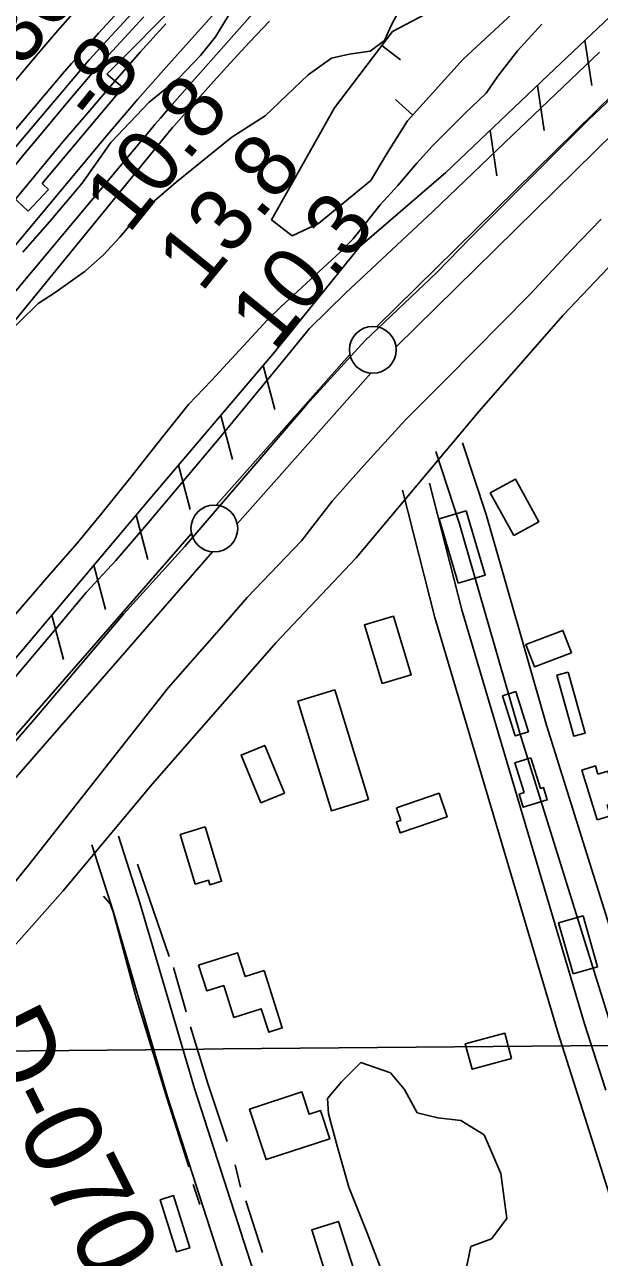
# Model space of a CAD drawing. Extents: x 3598634 to 3636690, y 517270 to 542944.
# Drawn here: x 3608565 to 3609179, y 528569 to 529886 of the extents above; entities that cross this region are included whole.
import ezdxf

# ---------------------------------------------------------------- set-up
doc = ezdxf.new("R2010")
doc.units = 0
for name, color, linetype in [('V-BLDG-OTLN', 7, 'Continuous'), ('V-BORW-LINE', 7, 'Continuous'), ('V-FLOD-BASE', 7, 'Continuous'), ('V-GRID-MAJR', 7, 'Continuous'), ('V-LEVE-TOET', 7, 'Continuous'), ('V-RIVR-EDGE', 7, 'Continuous'), ('V-RIVR-RANG', 7, 'Continuous'), ('V-RIVR-RANG-IDEN', 7, 'Continuous'), ('V-ROAD-CNTR', 7, 'Continuous'), ('V-RRAP-FSHR', 7, 'Continuous'), ('V-RRAP-RVMT', 7, 'Continuous'), ('V-SITE-VEGE', 7, 'Continuous'), ('V-SURV-LINE', 7, 'Continuous'), ('V-TOPO-DPTH', 7, 'Continuous'), ('V-TOPO-MINR', 7, 'Continuous'), ('V-TOPO-SHOR', 7, 'Continuous'), ('V-TOPO-WATR', 7, 'Continuous')]:
    doc.layers.add(name, color=color, linetype=linetype)

msp = doc.modelspace()

# ---------------------------------------------------------------- linework, layer by layer
at = {"layer": 'V-BLDG-OTLN'}
for points in [[(3609087.4, 529339.9), (3609062.3, 529385.6), (3609089.2, 529400.4), (3609114.2, 529354.7)], [(3609028, 529289.1), (3609007.8, 529357.9), (3609036.5, 529366.3), (3609056.7, 529297.5)], [(3608946.7, 529181.8), (3608927.8, 529244.4), (3608958.8, 529253.8), (3608977.6, 529191.1)], [(3609148.9, 529214.5), (3609109.4, 529199.7), (3609100.4, 529223.6), (3609139.9, 529238.5)], [(3609145.5, 529194.1), (3609163.7, 529128.7), (3609151.6, 529125.4), (3609133.4, 529190.8)], [(3608896.3, 529175.1), (3608932, 529057.9), (3608892.5, 529045.9), (3608856.8, 529163)], [(3609089.6, 529173.2), (3609103.1, 529130.3), (3609088.9, 529125.8), (3609075.4, 529168.7)], [(3608817, 529054.2), (3608796.1, 529105.3), (3608821.4, 529115.7), (3608842.4, 529064.6)], [(3609105.7, 529102.4), (3609115.9, 529069.7), (3609119.1, 529070.7), (3609123.2, 529057.6), (3609097.5, 529049.6), (3609093.2, 529063.7), (3609098.4, 529065.4), (3609088.6, 529097.1)], [(3609176.3, 529036.1), (3609160.1, 529089.3), (3609174.6, 529093.7), (3609177.3, 529085), (3609187.9, 529088.2), (3609198, 529055.1), (3609187.2, 529051.8), (3609190.6, 529040.5)], [(3608962, 529049), (3609007.6, 529064.5), (3609016.2, 529039.3), (3608966.1, 529022.2), (3608962.1, 529033.9), (3608966.6, 529035.4)], [(3608757.7, 529028.5), (3608775.2, 528970.6), (3608762.6, 528966.7), (3608761.1, 528971.6), (3608747.1, 528967.4), (3608731, 529020.4)], [(3609150.7, 528871.5), (3609135.2, 528926), (3609161.4, 528933.4), (3609176.9, 528878.9)], [(3608820.6, 528875.1), (3608840.1, 528813.8), (3608825.6, 528809.2), (3608817.6, 528834.3), (3608788.3, 528825), (3608777.5, 528859), (3608759.4, 528853.3), (3608750.6, 528880.8), (3608792.1, 528894.1), (3608800.3, 528868.7)], [(3609085.1, 528781.1), (3609042.9, 528769.7), (3609035.6, 528796.6), (3609077.8, 528808.1)], [(3608890.9, 528695.3), (3608822.7, 528673), (3608805.1, 528727), (3608861, 528745.3), (3608868.7, 528721.5), (3608881, 528725.5)], [(3608723.7, 528634.6), (3608741.2, 528578.8), (3608727.2, 528574.4), (3608709.7, 528630.2)], [(3608892.4, 528531.9), (3608871.5, 528598), (3608900.1, 528607), (3608921, 528540.9)]]:
    msp.add_lwpolyline(points, close=True, dxfattribs=at)
at = {"layer": 'V-BORW-LINE'}
for p, q in [((3608946.5, 529863.6), (3608966.4, 529848.5)), ((3608979.4, 529789.4), (3608960.9, 529806.1))]:
    msp.add_line(p, q, dxfattribs=at)
for points in [[(3608934.7, 529719.3), (3608878.9, 529673.6), (3608850.6, 529660.4), (3608828.6, 529677.4), (3608895.8, 529796.9), (3608957.9, 529878.5), (3609006.5, 529904.3), (3609074.6, 529975.4), (3609115.4, 530005.8), (3609131.2, 529971.9), (3609090.7, 529902), (3609033.3, 529849.2), (3608973.8, 529783.2), (3608951, 529746.9), (3608934.7, 529719.3)], [(3608955, 529753.3), (3608973.8, 529783.2), (3609033.3, 529849.2), (3609090.7, 529902), (3609131.2, 529971.9), (3609115.4, 530005.8), (3609074.6, 529975.4), (3609006.5, 529904.3), (3608957.9, 529878.5), (3608899.4, 529801.6)], [(3608934.7, 529719.3), (3608951, 529746.9), (3608954.4, 529752.3)]]:
    msp.add_lwpolyline(points, dxfattribs=at)
at = {"layer": 'V-FLOD-BASE'}
msp.add_lwpolyline([(3608057.5, 528550.9), (3608164.4, 528673.2), (3608262.3, 528787.8), (3608368.5, 528912.2), (3608466.3, 529018.5), (3608577.4, 529146.3), (3608670.3, 529256.1), (3608736, 529328.3), (3608866, 529479.8), (3608928.2, 529547.9), (3609005.7, 529621.5), (3609041.3, 529658.3), (3609167, 529784), (3609227.1, 529840.9)], dxfattribs=at)
at = {"layer": 'V-GRID-MAJR'}
msp.add_spline([(3602797.9, 528737.7), (3608075.8, 528784.9), (3613353.8, 528832.9), (3618631.7, 528881.6), (3623909.7, 528931.1), (3629187.6, 528981.4), (3634465.5, 529032.5), (3634465.6, 529032.5)], degree=3, dxfattribs=at)
at = {"layer": 'V-LEVE-TOET'}
for points in [[(3609179.1, 529856.4), (3609077.8, 529759.9), (3609001, 529686.3), (3608908.1, 529599.5), (3608869, 529561.3), (3608835.5, 529520.3), (3608770.5, 529441.1), (3608695, 529351.4), (3608662.1, 529313.2), (3608630.7, 529279.2), (3608596.5, 529238.2), (3608544.7, 529177), (3608478.4, 529100.6), (3608366.6, 528972.8), (3608294.6, 528891.5), (3608219.1, 528804)], [(3608107.4, 528449.1), (3608214.3, 528584.6), (3608308.6, 528684.6), (3608364.5, 528749.9), (3608447.7, 528845.1), (3608484, 528888.9), (3608521.8, 528929.9), (3608569.3, 528988.2), (3608667.8, 529113.3), (3608718.2, 529177.2), (3608772.7, 529239.1), (3608802.7, 529273.8), (3608860.7, 529334.2), (3608893.5, 529376.6), (3608927.1, 529414.8), (3608971.8, 529463.5), (3609015.1, 529507.2), (3609104.5, 529597.5), (3609149.2, 529645.4), (3609180.6, 529678.1)]]:
    msp.add_lwpolyline(points, dxfattribs=at)
at = {"layer": 'V-RIVR-EDGE'}
msp.add_lwpolyline([(3608563, 529642.8), (3608591.3, 529675.1), (3608626.2, 529716.5), (3608656.9, 529760.2), (3608697.8, 529803.3), (3608729.1, 529828.5), (3608752.6, 529853), (3608768.8, 529872.8), (3608782.7, 529895.6)], dxfattribs=at)
at = {"layer": 'V-ROAD-CNTR'}
for points in [[(3606832.7, 526952), (3606973.8, 527100.2), (3607148.9, 527293), (3607268.5, 527428.8), (3607385.5, 527558.8), (3607495.8, 527683.5), (3607551.8, 527751.4), (3607615.9, 527832.2), (3607705.6, 527929.3), (3607806.9, 528046.9), (3607941.6, 528200.2), (3608081.9, 528357.7), (3608279.1, 528592.5), (3608364.5, 528689.3), (3608525, 528869.3), (3608605.5, 528959.8), (3608701.5, 529074.5), (3608833.1, 529225.4), (3608919, 529316.1), (3609050.5, 529472.9), (3609139.7, 529575.2), (3609208.8, 529647.9)], [(3609032.5, 529439.1), (3609057.8, 529362.5), (3609122.5, 529137.2), (3609224.5, 528811), (3609325.6, 528484.3), (3609398.3, 528245.3), (3609508.2, 527898.9), (3609537.5, 527827)], [(3609004, 529429.7), (3609029.1, 529353.6), (3609093.8, 529128.6), (3609195.8, 528802.1), (3609210.9, 528753.6)], [(3608968.4, 529388.6), (3609003, 529252.5), (3609134.5, 528809.2), (3609247.5, 528453.6), (3609349.1, 528118.6), (3609496.3, 527647.9), (3609590.3, 527350.1)], [(3608997.4, 529396), (3609032, 529260.5), (3609163.1, 528818), (3609185.6, 528747.3)], [(3608665.2, 529018.6), (3608688, 528947.3), (3608746.2, 528749.1), (3608848.5, 528432), (3608946.8, 528139.6), (3609111.4, 527605.9), (3609243, 527178.6), (3609394.6, 526698), (3609572.4, 526137.8), (3609769.5, 525515.2), (3610214.2, 524114.9)], [(3608636.6, 529009.4), (3608659.4, 528938.5), (3608717.5, 528740.2), (3608820.1, 528422.7), (3608918.3, 528130.4), (3609082.7, 527597.1), (3609214.4, 527169.6), (3609366, 526689), (3609543.8, 526128.7), (3609740.9, 525506.2), (3610185.6, 524105.8)]]:
    msp.add_lwpolyline(points, dxfattribs=at)
at = {"layer": 'V-RRAP-FSHR'}
for p, q in [((3609163.4, 529869.3), (3609170.7, 529821)), ((3609112.7, 529821.1), (3609120, 529772.8)), ((3609062, 529772.8), (3609069.3, 529724.5)), ((3608819.8, 529521.8), (3608832.2, 529474.6)), ((3608774.5, 529468.4), (3608786.8, 529421.2)), ((3608729.2, 529415.1), (3608741.5, 529367.8)), ((3608683.9, 529361.7), (3608696.4, 529314.5)), ((3608638.8, 529308.2), (3608651.3, 529261)), ((3608593.7, 529254.7), (3608606.2, 529207.5))]:
    msp.add_line(p, q, dxfattribs=at)
for points in [[(3609004.6, 529719.2), (3609014.7, 529727.8), (3609124.2, 529832), (3609276.1, 529976.3), (3609434.6, 530132.6), (3609483.1, 530170), (3609560.8, 530232.8)], [(3605375.2, 525433.8), (3605456, 525580.5), (3605630.7, 525877.6), (3605746.8, 526080.3), (3605800.6, 526159), (3605867.3, 526231.6), (3605948.4, 526309.6), (3606191.9, 526556.5), (3606564.8, 526949.6), (3606877.9, 527278.9), (3607054.8, 527479.5), (3607380.2, 527856.8), (3607669.2, 528199.4), (3608066.5, 528645), (3608475.6, 529114.7), (3608696.8, 529377), (3608831.9, 529536), (3608922.8, 529648.8), (3609014.7, 529727.8), (3609124.2, 529832), (3609276.1, 529976.3)], [(3608141.4, 528731), (3608475.6, 529114.7), (3608696.8, 529377), (3608831.9, 529536), (3608833.8, 529538.4)]]:
    msp.add_lwpolyline(points, dxfattribs=at)
at = {"layer": 'V-RRAP-RVMT'}
for p, q in [((3608652.7, 529833.1), (3608749.1, 529930.2)), ((3608669.6, 529818.9), (3608652.7, 529833.1)), ((3608583.6, 529716.3), (3608669.6, 529818.9)), ((3608590.4, 529709.9), (3608583.6, 529716.3)), ((3608550.3, 529703.6), (3608568.6, 529686.5)), ((3608568.6, 529686.5), (3608590.4, 529709.9))]:
    msp.add_line(p, q, dxfattribs=at)
at = {"layer": 'V-SITE-VEGE'}
for points in [[(3608516.5, 529526.7), (3608579.3, 529587.9), (3608597.5, 529599.6), (3608629.6, 529622.5), (3608649.1, 529639.9), (3608666.6, 529658.7), (3608688.3, 529684.4), (3608726.7, 529717.7), (3608786, 529765.6), (3608821.6, 529788.4), (3608867.7, 529832.2), (3608892.8, 529850.2), (3608911.6, 529854.4), (3608933.9, 529857.8), (3608949.3, 529868.9), (3608956.3, 529884.9), (3608971.7, 529914.1)], [(3609117.2, 529886.5), (3609091.3, 529858), (3609070.3, 529830.9), (3609057.8, 529812.8), (3609034.7, 529790.6), (3609000.5, 529756.6), (3608983.7, 529737.8), (3608963.5, 529714.2), (3608944.6, 529693.4), (3608928.5, 529673.2), (3608915.9, 529657.2), (3608902, 529642.7), (3608838.4, 529584.3), (3608824.4, 529570.4), (3608764.4, 529505.8), (3608739.9, 529480.1), (3608712.7, 529446.1), (3608678.4, 529402.3), (3608647.7, 529364.1), (3608621.1, 529332.1), (3608593.2, 529300.2), (3608537.2, 529235.6)], [(3608963.1, 528510.3), (3608930.4, 528595.6), (3608911.3, 528643.7), (3608899, 528686.3), (3608889.5, 528722), (3608888.2, 528738.5), (3608903.3, 528756.3), (3608924, 528776.9), (3608955.6, 528765.8), (3608970.6, 528747.9), (3608984.3, 528723.1), (3609006.2, 528717.6), (3609030.9, 528714.8), (3609055.6, 528699.6), (3609073.4, 528658.3), (3609080.1, 528610.2), (3609063.5, 528588.3), (3609041.5, 528580.1), (3609037.4, 528559.6)]]:
    msp.add_lwpolyline(points, dxfattribs=at)
at = {"layer": 'V-SURV-LINE'}
for points in [[(3608940.6, 529563.1), (3609471.7, 530085.8)], [(3609492.7, 530064.4), (3608961.6, 529541.7)], [(3608769.5, 529372.4), (3608912.4, 529533.4)], [(3608934.8, 529513.5), (3608791.9, 529352.5)], [(3607846.3, 528313.6), (3608743, 529342.3)], [(3608765.6, 529322.6), (3607869, 528293.9)]]:
    msp.add_lwpolyline(points, dxfattribs=at)
for centre in [(3608936.8, 529538.4), (3608767.4, 529347.5)]:
    msp.add_circle(centre, 25, dxfattribs=at)
at = {"layer": 'V-TOPO-DPTH'}
for points in [[(3607050.1, 527933.9), (3607754.7, 528800.4), (3607773.1, 528823.2), (3607791.6, 528845.9), (3607810, 528868.6), (3607828.4, 528891.4), (3608108.5, 529237.4), (3608193.3, 529341.4), (3608278.5, 529445), (3608364.4, 529548), (3608450.7, 529650.7), (3608605.4, 529833.4), (3608614.8, 529844.4), (3608624.3, 529855.2), (3608634, 529866), (3608643.7, 529876.7), (3609104.3, 530376.6)], [(3609104.3, 530376.6), (3608643.7, 529876.7), (3608634, 529866), (3608624.3, 529855.2), (3608614.8, 529844.4), (3608605.4, 529833.4), (3608450.7, 529650.7), (3608364.4, 529548), (3608278.5, 529445), (3608193.3, 529341.4), (3608108.5, 529237.4), (3607828.4, 528891.4), (3607810, 528868.6), (3607791.6, 528845.9), (3607773.1, 528823.2), (3607754.7, 528800.4), (3607050.1, 527933.9)], [(3608991.3, 530147.9), (3608718.8, 529843.8), (3608702.1, 529824.9), (3608685.4, 529806), (3608669, 529786.8), (3608652.7, 529767.5), (3608514.7, 529602.5), (3608429.7, 529500.5), (3608344.9, 529398.2), (3608260.6, 529295.6), (3608176.6, 529192.7), (3607892.1, 528842.9), (3607872.7, 528819), (3607853.3, 528795.1), (3607833.8, 528771.2), (3607814.4, 528747.3), (3607476.4, 528331.4)], [(3607476.4, 528331.4), (3607814.4, 528747.3), (3607833.8, 528771.2), (3607853.3, 528795.1), (3607872.7, 528819), (3607892.1, 528842.9), (3608176.6, 529192.7), (3608260.6, 529295.6), (3608344.9, 529398.2), (3608429.7, 529500.5), (3608514.7, 529602.5), (3608652.7, 529767.5), (3608669, 529786.8), (3608685.4, 529806), (3608702.1, 529824.9), (3608718.8, 529843.8), (3608991.3, 530147.9)], [(3607486.3, 528518.1), (3607579.8, 528634.5), (3607720.9, 528809.6), (3607744.1, 528838.3), (3607767.2, 528867), (3607790.4, 528895.7), (3607813.6, 528924.4), (3607874.8, 529000.2), (3607928.8, 529066.7), (3607982.8, 529133.1), (3608037.1, 529199.3), (3608091.5, 529265.4), (3608556.6, 529828.2), (3608577, 529852.6), (3608597.7, 529876.7), (3608618.7, 529900.6)], [(3608618.7, 529900.6), (3608597.7, 529876.7), (3608577, 529852.6), (3608556.6, 529828.2), (3608091.5, 529265.4), (3608037.1, 529199.3), (3607982.8, 529133.1), (3607928.8, 529066.7), (3607874.8, 529000.2), (3607813.6, 528924.4), (3607790.4, 528895.7), (3607767.2, 528867), (3607744.1, 528838.3), (3607720.9, 528809.6), (3607579.8, 528634.5), (3607486.3, 528518.1)], [(3608692, 529894.3), (3608646.1, 529844.4), (3608644.3, 529842.5), (3608642.6, 529840.5), (3608640.9, 529838.6), (3608639.2, 529836.6), (3608611, 529803.4), (3608595.3, 529784.7), (3608579.6, 529765.9), (3608564.1, 529747.1), (3608548.7, 529728.2), (3607821.9, 528831.1), (3607819.1, 528827.7), (3607816.4, 528824.3), (3607813.7, 528821), (3607811, 528817.6), (3607746.5, 528737.6), (3607711.5, 528694.3), (3607676.6, 528650.8), (3607641.8, 528607.4), (3607607, 528563.8)], [(3607607, 528563.8), (3607641.8, 528607.4), (3607676.6, 528650.8), (3607711.5, 528694.3), (3607746.5, 528737.6), (3607811, 528817.6), (3607813.7, 528821), (3607816.4, 528824.3), (3607819.1, 528827.7), (3607821.9, 528831.1), (3608548.7, 529728.2), (3608564.1, 529747.1), (3608579.6, 529765.9), (3608595.3, 529784.7), (3608611, 529803.4), (3608639.2, 529836.6), (3608640.9, 529838.6), (3608642.6, 529840.5), (3608644.3, 529842.5), (3608646.1, 529844.4), (3608692, 529894.3)], [(3608826.3, 529889.7), (3608805.1, 529867.4), (3608784.2, 529844.8), (3608763.6, 529821.9), (3608724.2, 529777.5), (3608723.4, 529776.7), (3608722.7, 529775.9), (3608721.3, 529774.2), (3607992.3, 528881.1), (3607976.2, 528861.3), (3607960, 528841.5), (3607943.9, 528821.7), (3607927.7, 528801.9), (3607900.6, 528768.6), (3607898, 528765.4), (3607895.5, 528762.3), (3607892.9, 528759.1), (3607890.3, 528755.9), (3607830.2, 528681.3), (3607797.5, 528640.8), (3607764.9, 528600.3), (3607732.3, 528559.8)]]:
    msp.add_lwpolyline(points, dxfattribs=at)
at = {"layer": 'V-TOPO-MINR'}
for points in [[(3607269.9, 528037.4), (3607833.2, 528728.4), (3607853.7, 528753.6), (3607874.2, 528778.8), (3607894.7, 528804), (3607915.2, 528829.2), (3608013, 528949.2), (3608082.5, 529034.2), (3608152.3, 529119.1), (3608222.4, 529203.7), (3608292.8, 529288.1), (3608697.7, 529771.9), (3608703.8, 529779.1), (3608709.9, 529786.2), (3608716, 529793.3), (3608722.2, 529800.4), (3609349.8, 530509.1)], [(3607050.1, 527933.9), (3607754.7, 528800.4), (3607773.1, 528823.2), (3607791.6, 528845.9), (3607810, 528868.6), (3607828.4, 528891.4), (3608108.5, 529237.4), (3608193.3, 529341.4), (3608278.5, 529445), (3608364.4, 529548), (3608450.7, 529650.7), (3608605.4, 529833.4), (3608614.8, 529844.4), (3608624.3, 529855.2), (3608634, 529866), (3608643.7, 529876.7), (3609104.3, 530376.6)], [(3607538.9, 528507.8), (3607788.1, 528815.6), (3607796, 528825.4), (3607803.9, 528835.2), (3607811.9, 528844.9), (3607819.8, 528854.7), (3608327.2, 529481.3), (3608377.6, 529543), (3608428.1, 529604.5), (3608479.1, 529665.6), (3608530.4, 529726.5), (3608622.3, 529835), (3608627.9, 529841.5), (3608633.5, 529847.9), (3608639.1, 529854.2), (3608644.9, 529860.5), (3608795.9, 530024.4)], [(3607486.3, 528518.1), (3607579.8, 528634.5), (3607720.9, 528809.6), (3607744.1, 528838.3), (3607767.2, 528867), (3607790.4, 528895.7), (3607813.6, 528924.4), (3607874.8, 529000.2), (3607928.8, 529066.7), (3607982.8, 529133.1), (3608037.1, 529199.3), (3608091.5, 529265.4), (3608556.6, 529828.2), (3608577, 529852.6), (3608597.7, 529876.7), (3608618.7, 529900.6)], [(3607607, 528563.8), (3607641.8, 528607.4), (3607676.6, 528650.8), (3607711.5, 528694.3), (3607746.5, 528737.6), (3607811, 528817.6), (3607813.7, 528821), (3607816.4, 528824.3), (3607819.1, 528827.7), (3607821.9, 528831.1), (3608548.7, 529728.2), (3608564.1, 529747.1), (3608579.6, 529765.9), (3608595.3, 529784.7), (3608611, 529803.4), (3608639.2, 529836.6), (3608640.9, 529838.6), (3608642.6, 529840.5), (3608644.3, 529842.5), (3608646.1, 529844.4), (3608692, 529894.3)], [(3607616.8, 528543), (3607659.9, 528596.7), (3607703, 528650.4), (3607746.2, 528704), (3607777.6, 528742.9), (3607805.2, 528777), (3607832.7, 528811.1), (3607860.3, 528845.1), (3607888, 528879.2), (3608477.2, 529604.9), (3608507.5, 529642), (3608537.8, 529679), (3608568.4, 529715.9), (3608599, 529752.7), (3608607.7, 529763.1), (3608634.3, 529794.4), (3608661.1, 529825.6), (3608688.3, 529856.4), (3608715.7, 529887)], [(3607732.3, 528559.8), (3607764.9, 528600.3), (3607797.5, 528640.8), (3607830.2, 528681.3), (3607890.3, 528755.9), (3607892.9, 528759.1), (3607895.5, 528762.3), (3607898, 528765.4), (3607900.6, 528768.6), (3607927.7, 528801.9), (3607943.9, 528821.7), (3607960, 528841.5), (3607976.2, 528861.3), (3607992.3, 528881.1), (3608721.3, 529774.2), (3608722.7, 529775.9), (3608723.4, 529776.7), (3608724.2, 529777.5), (3608763.6, 529821.9), (3608784.2, 529844.8), (3608805.1, 529867.4), (3608826.3, 529889.7)]]:
    msp.add_lwpolyline(points, dxfattribs=at)
at = {"layer": 'V-TOPO-SHOR'}
for p, q in [((3608723.8, 528878.2), (3608737.2, 528831.1)), ((3608789.7, 528667.3), (3608795.5, 528643.6)), ((3608745, 528646.5), (3608751.9, 528624.9)), ((3608801, 528629.1), (3608818.8, 528573.7))]:
    msp.add_line(p, q, dxfattribs=at)
for points in [[(3608685.4, 528988.6), (3608710.9, 528914), (3608719.2, 528890)], [(3608649.1, 528954.6), (3608656, 528946.2), (3608659.5, 528937.8), (3608683.6, 528847.2), (3608716.7, 528739.2), (3608740.2, 528665.3)], [(3608742, 528815), (3608760.6, 528754.4), (3608781, 528692.3)]]:
    msp.add_lwpolyline(points, dxfattribs=at)
at = {"layer": 'V-TOPO-WATR'}
msp.add_lwpolyline([(3607476.4, 528331.4), (3607814.4, 528747.3), (3607833.8, 528771.2), (3607853.3, 528795.1), (3607872.7, 528819), (3607892.1, 528842.9), (3608176.6, 529192.7), (3608260.6, 529295.6), (3608344.9, 529398.2), (3608429.7, 529500.5), (3608514.7, 529602.5), (3608652.7, 529767.5), (3608669, 529786.8), (3608685.4, 529806), (3608702.1, 529824.9), (3608718.8, 529843.8), (3608991.3, 530147.9)], dxfattribs=at)

# ---------------------------------------------------------------- texts
at = {"layer": 'V-RIVR-RANG'}
for s, p in [('-36', (3608543.1, 529815.3)), ('-8', (3608641.2, 529777.5)), ('10.8', (3608675.7, 529661.2)), ('13.8', (3608753.5, 529598.5)), ('10.3', (3608831.4, 529535.7))]:
    msp.add_text(s, height=67, rotation=50.9683, dxfattribs=at).set_placement(p)
at = {"layer": 'V-RIVR-RANG-IDEN'}
msp.add_text('D-070', height=83, rotation=296.6054, dxfattribs=at).set_placement((3608503, 528809.8))

doc.saveas('drawing.dxf')
